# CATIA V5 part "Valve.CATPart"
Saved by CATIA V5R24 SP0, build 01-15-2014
Part number: Valve
Bounding box of the stored display mesh (mm): x -31.895 to 31.895, y 0 to 132, z -31.991 to 31.991
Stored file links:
  E:\Desktop_RNH\학부 CAD 수업 자료\[CAD_V2]강의자료(CAD)_2017년 이후\툴바예제\DMU Kinematics_2017\Example\Valve.CATPart

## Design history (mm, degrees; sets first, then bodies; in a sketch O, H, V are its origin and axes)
Body1 (main body)
  Sketch1 on xy-plane, origin (0, 0, 0), H (1, 0, 0), V (0, 1, 0)
    line L1 (20, 1.1146) -> (20, 5)
    line L2 (20, 5) -> (11.2724, 8.5061)
    line L3 (5, 17.7853) -> (5, 108.7077)
    line L4 (0, 129.944) -> (0, 0)
    line L5 (32, 132) -> (32, 127.96)
    arc A1 centre (15, 17.7853) radius 10 from (11.2724, 8.5061) to (5, 17.7853) cw
    line L6 (32, 127.96) -> (10.6727, 117.7229)
    arc A2 centre (15, 108.7077) radius 10 from (10.6727, 117.7229) to (5, 108.7077) ccw
    arc A3 centre (0, 380) radius 250.056 from (0, 129.944) to (32, 132) ccw
    point P10 (0, 380)
    arc A4 centre (0, 180) radius 180 from (0, 0) to (20, 1.1146) ccw
    point P12 (0, 180)
    radius A1 = 10
    radius A2 = 10
    vertical: L1 V, L3 V, L5 V
    tangency: A1 L2, A1 L3, A2 L6, A2 L3
    coincidence: P10 V, P12 V
  Shaft1: profile Sketch1, axis Sketch1.L4, angle 360
  Point1: type Center, Curve edge [face of Shaft1 from Sketch1.A3 | face of Shaft1 from Sketch1.L5]
  Plane1: type OffsetPt, RefPlane zx-plane, RefPoint Point1
  Point2: (0, 0, 0)
  Sketch2 on zx-plane, origin (0, 0, 0), H (-1, 0, 0), V (0, 0, 1)
    point P1 (40, 0)
    line L1 (40, 0) -> (-40, 0)
    coincidence: P1 H
    horizontal: L1 H
  Project1: ToProject Sketch2, Support Shaft1
  Plane2: type Tangent, Support face of Shaft1 from Sketch1.A4, RefPoint Point2
  Sketch3 on Plane2, origin (0, 0, 0), H (-1, 0, 0), V (0, 0, 1)
    line L1 (25, 0) -> (-25, 0)
    point P1 (25, 0)
    coincidence: P1 H
    horizontal: L1 H
  Project2: ToProject Sketch3, Support Shaft1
